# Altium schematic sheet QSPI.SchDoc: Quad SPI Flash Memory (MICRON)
size A4; Date: 25-FEB-2015; Author: A.B; CompanyName: STMicroelectronics; Address1: 12, Rue Jules HOROWITZ; Address2: 38019 Grenoble; Address3: FRANCE; DocumentNumber: MB1191; Revision: B-02; SheetNumber: 5; SheetTotal: 13; Project: STM32F746G-DISCO
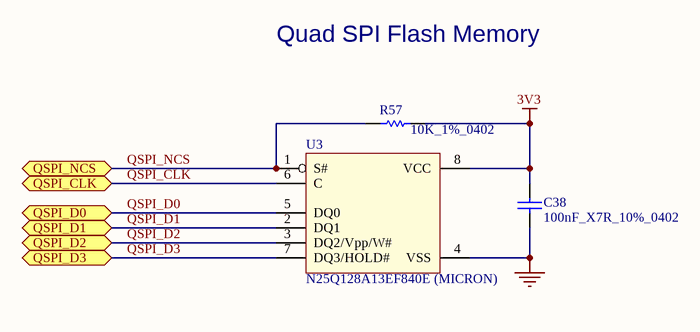
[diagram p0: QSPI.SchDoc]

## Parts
C38  100nF_X7R_10%_0402  [0402C]
R57  10K_1%_0402  [0402R]
U3  N25Q128A13EF840E (MICRON)  [V-PDFN-8 8x6]

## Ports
QSPI_CLK, QSPI_D0, QSPI_D1, QSPI_D2, QSPI_D3, QSPI_NCS

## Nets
3V3: C38.2 R57.2 U3.8(VCC)
GND: C38.1 U3.4(VSS)
QSPI_CLK: U3.6(C) ; port QSPI_CLK
QSPI_D0: U3.5(DQ0) ; port QSPI_D0
QSPI_D1: U3.2(DQ1) ; port QSPI_D1
QSPI_D2: U3.3(DQ2/Vpp/W#) ; port QSPI_D2
QSPI_D3: U3.7(DQ3/HOLD#) ; port QSPI_D3
QSPI_NCS: R57.1 U3.1(S#) ; port QSPI_NCS

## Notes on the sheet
- Quad SPI Flash Memory

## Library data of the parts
C38 = Cap_100nF_X7R_10%_0402: Capacitor,100nF,16V,X7R,10%,0402,YAGEO; Manuf_Part_1: CC0402KRX7R7BB104
R57 = Res_10K_1%_0402: Resistor,10K,0402,1%,YAGEO; Manuf_Part_1: RC0402FR-0710KL
U3 = N25Q128A13EF840E: 128Mb, 3V, Multiple I/O Serial Flash Memory, Quad/Dual; Manuf_Part_2: N25Q256A13EF840E; Manuf_Part_3: N25Q512A13EF840E; ECCN_US/EU: 3A991/NEC; Order: N25Q128A13EF840F-ND; Provided: ST; Ref St: 9171973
